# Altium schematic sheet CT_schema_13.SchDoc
size 386 x 385 mm
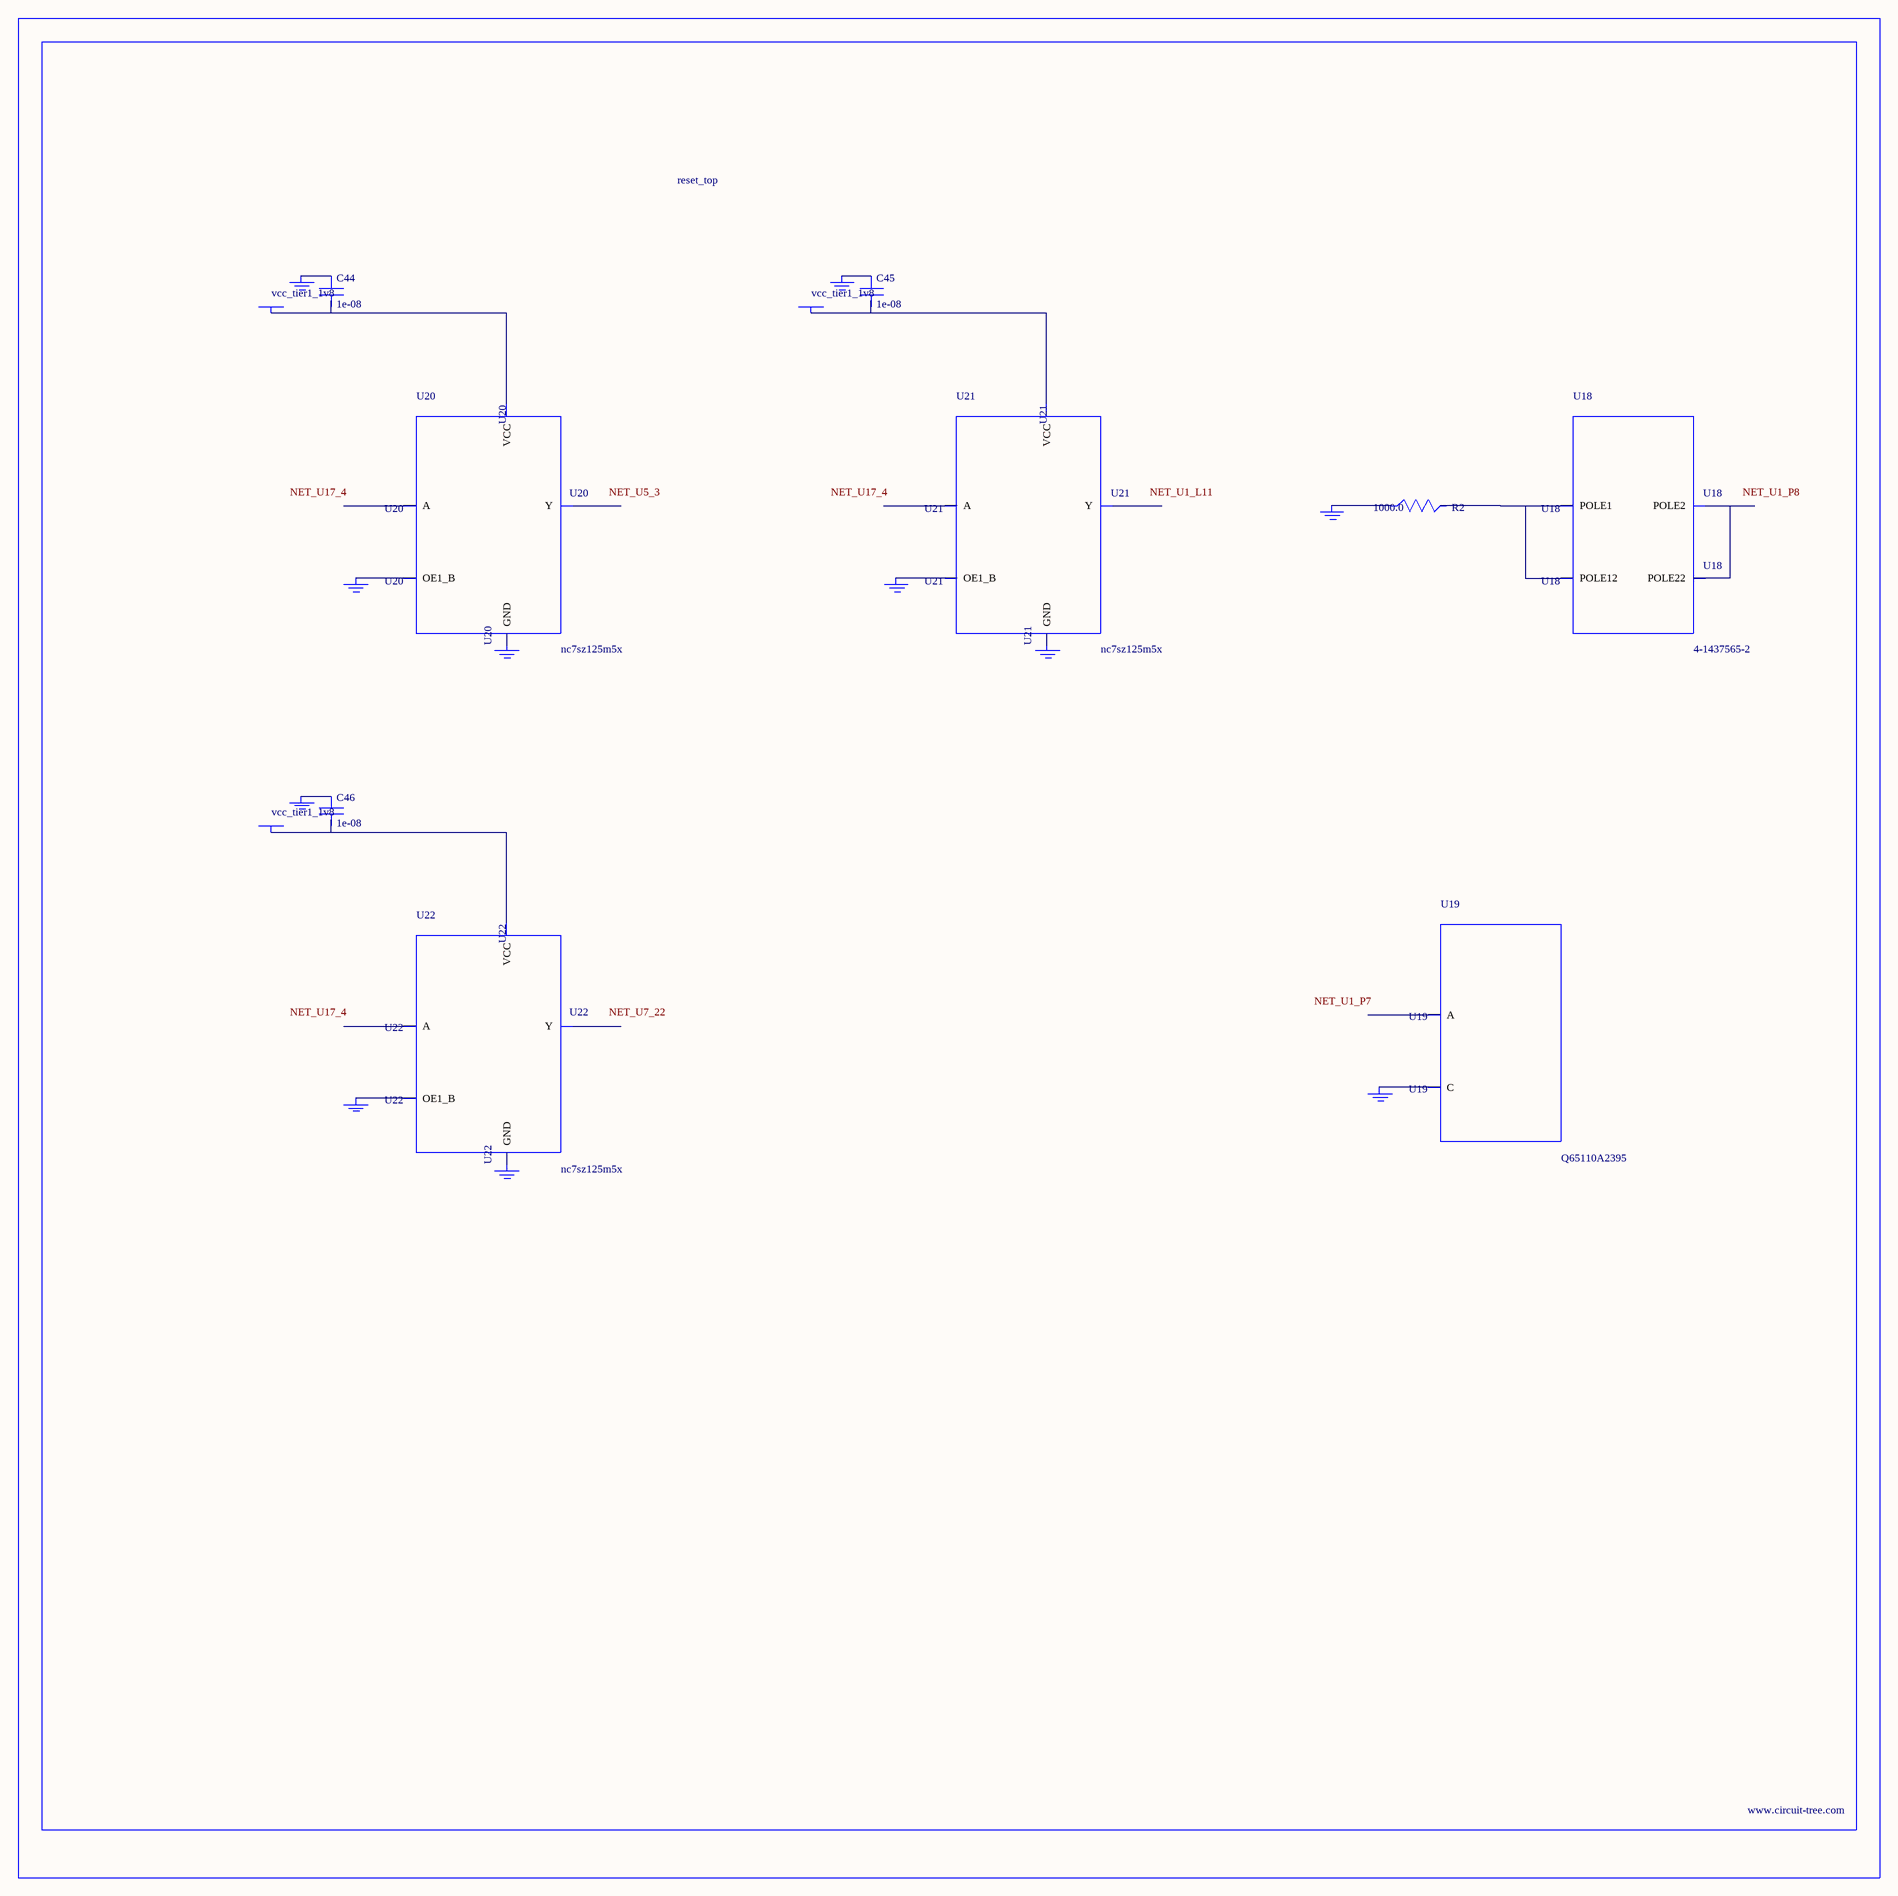
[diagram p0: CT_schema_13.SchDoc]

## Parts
BORDER12  (no value)
C44  1e-08  [C0402]
C45  1e-08  [C0402]
C46  1e-08  [C0402]
GND_INSTANCE_12_0  (no value)
GND_INSTANCE_12_1  (no value)
GND_INSTANCE_12_2  (no value)
GND_INSTANCE_12_3  (no value)
GND_INSTANCE_12_4  (no value)
GND_INSTANCE_12_5  (no value)
GND_INSTANCE_12_6  (no value)
GND_INSTANCE_12_7  (no value)
GND_INSTANCE_12_8  (no value)
GND_INSTANCE_12_9  (no value)
GND_INSTANCE_12_10  (no value)
POWER_INSTANCE_12_0  vcc_tier1_1v8
POWER_INSTANCE_12_1  vcc_tier1_1v8
POWER_INSTANCE_12_2  vcc_tier1_1v8
R2  1000.0  [R0603]
U18  4-1437565-2  [SW_4-1437565-2]
U19  Q65110A2395  [LGM67K-G1J2-24-Z]
U20  nc7sz125m5x  [NC7SZ125M5X]
U21  nc7sz125m5x  [NC7SZ125M5X]
U22  nc7sz125m5x  [NC7SZ125M5X]

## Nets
NetC44_1: C44.1 GND_INSTANCE_12_2.0(GND)
NetC44_2: C44.2 POWER_INSTANCE_12_0.0(PWR) U20.5(VCC)
NetC45_1: C45.1 GND_INSTANCE_12_5.0(GND)
NetC45_2: C45.2 POWER_INSTANCE_12_1.0(PWR) U21.5(VCC)
NetC46_1: C46.1 GND_INSTANCE_12_8.0(GND)
NetC46_2: C46.2 POWER_INSTANCE_12_2.0(PWR) U22.5(VCC)
NetGND_INSTANCE_12_0_0: GND_INSTANCE_12_0.0(GND) R2.1
NetGND_INSTANCE_12_1_0: GND_INSTANCE_12_1.0(GND) U19.C
NetGND_INSTANCE_12_3_0: GND_INSTANCE_12_3.0(GND) U20.1(OE1_B)
NetGND_INSTANCE_12_4_0: GND_INSTANCE_12_4.0(GND) U20.3(GND)
NetGND_INSTANCE_12_6_0: GND_INSTANCE_12_6.0(GND) U21.1(OE1_B)
NetGND_INSTANCE_12_7_0: GND_INSTANCE_12_7.0(GND) U21.3(GND)
NetGND_INSTANCE_12_9_0: GND_INSTANCE_12_9.0(GND) U22.1(OE1_B)
NetGND_INSTANCE_12_10_0: GND_INSTANCE_12_10.0(GND) U22.3(GND)
NetR2_2: R2.2 U18.1(POLE1) U18.2(POLE12)
NetU18_3: U18.3(POLE2) U18.4(POLE22)

Not connected (* = marked no-connect by the designer): U19 A; U20 2(A) 4(Y); U21 2(A) 4(Y); U22 2(A) 4(Y)

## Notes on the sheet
- Labels drawn without touching a wire or pin: NET_U1_L11, NET_U1_P7, NET_U1_P8, NET_U5_3, NET_U7_22, NET_U17_4

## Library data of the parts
BORDER12 = BORDER_PAGE12
C44-C46 = C0402C103K3RAC
GND_INSTANCE_12_0-GND_INSTANCE_12_10 = GND
POWER_INSTANCE_12_0-POWER_INSTANCE_12_2 = PWR
R2 = RC0603JR-071KL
